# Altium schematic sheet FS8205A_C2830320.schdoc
size 127 x 101 mm
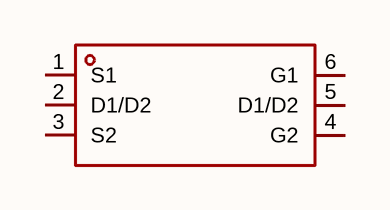
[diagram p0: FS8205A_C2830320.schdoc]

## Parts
Q?  fs8205a  [SOT-23-6_L2.9-W1.6-P0.95-LS2.8-BR]  (value not drawn)

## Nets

Not connected (* = marked no-connect by the designer): Q? 1(S1) 2(D1/D2) 3(S2) 4(G2) 5(D1/D2) 6(G1)

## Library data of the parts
Q? = fs8205a: 数量:2个N沟道;漏源电压(Vdss):20V;连续漏极电流(Id):6A;导通电阻(RDS(on)):31.5mΩ@2.5V;耗散功率(Pd):1.5W;阈值电压(Vgs(th)):1.2V;; Manufacturer: TECH PUBLIC(台舟); Symbol: FS8205A_C2830320; AddInBom: yes; ModelId: 18da8f6c14a34920b3e136b5c401a119; ModelName: SOT-23-6_L2.9-W1.6-H1.5-LS2.8-P0.95; ModelTransform: 110.73671,114.173,0,180,0,0,0.001,-0.003,0; Number: 2个N沟道; Drain to Source Voltage: 20V; Current - Continuous Drain(Id): 6A; Pd - Power Dissipation: 1.5W; Gate Threshold Voltage (Vgs(th)): 1.2V; Gate Charge(Qg): 5.7nC@4.5V; Input Capacitance(Ciss): 466pF; Reverse Transfer Capacitance (Crss@Vds): 58pF; Configuration: 共源; Type: N沟道; Output Capacitance(Coss): 65pF; Vgs: ±10V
